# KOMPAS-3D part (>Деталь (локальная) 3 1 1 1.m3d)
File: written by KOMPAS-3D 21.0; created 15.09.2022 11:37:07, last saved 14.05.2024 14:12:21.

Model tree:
1. Эскиз:1

Referenced files in C:\Program Files\Ascon\Libs\EasySteel\: Rolled metal.kle, StandartSolutions.kle, DSTVProperties.lpt
Referenced files in W:\Шаблоны чертежей\: Констр. чертеж А3 гориз. перв. лист.cdt
Referenced files in C:\Program Files\Ascon\Libs\EasySteel\BeltEndings\: 
Referenced files in C:\Program Files\Ascon\Libs\EasySteel\Punctures\: 
Referenced files in C:\Program Files\Ascon\Libs\EasySteel\Insulations\: 
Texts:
  Уголок равнополочный по ГОСТ 8509-93 (Спец)
  config2DpacketName
  config2DstdSizeID
  Констр. чертеж А3 гориз. перв. лист.cdt
  Болт ГОСТ 22353-77
  Шайба ГОСТ 22355-77
  Гайка ГОСТ 22354-77
  Нормальная пружинная шайба ГОСТ 6402-70 (исп. 1)
  SeaRox SL 436
  Сталь 09Г2С ГОСТ 19281-2014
